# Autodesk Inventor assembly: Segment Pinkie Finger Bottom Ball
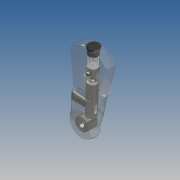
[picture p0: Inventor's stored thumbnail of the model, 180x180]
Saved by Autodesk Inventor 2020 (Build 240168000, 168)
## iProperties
Created: 2019-10
Part Number: Segment Pinkie Finger Bottom Ball
Document SubType Name: Assembly
Designer: yello
Author: yello
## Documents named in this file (8)
- C:\Users\yello\Documents\Mechanical Hand\Prototype 2 (Realistic Hand)\Segment Pinkie Finger Bottom Ball.iam
- C:\Users\yello\Documents\Mechanical Hand\Prototype 2 (Realistic Hand)\Segment Pinkie Finger Bottom.ipt
- C:\Users\yello\Documents\Mechanical Hand\Prototype 2 (Realistic Hand)\Lock.ipt
- C:\Users\yello\Documents\Mechanical Hand\Prototype 2 (Realistic Hand)\Ball.ipt
- C:\Users\yello\Documents\Mechanical Hand\Prototype 2 (Realistic Hand)\Plug 3.ipt
- C:\Users\yello\Documents\Mechanical Hand\Prototype 2 (Realistic Hand)\Push Part.ipt
- C:\Users\yello\Documents\Mechanical Hand\Prototype 2 (Realistic Hand)\Spring.ipt
- C:\Users\yello\Documents\Mechanical Hand\Prototype 2 (Realistic Hand)\Bearings.iam
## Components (8 placed, 7 different names)
1. Segment Pinkie Finger Bottom:1 — Mate:5, Mate:6, Mate:9, Mate:10, Mate:11, Mate:12, Mate:13, Mate:14, Flush:1
2. Ball:1 — Mate:6
3. Ball:2 — Mate:5
4. Push Part:1 — Mate:7, Mate:8, Mate:9
5. Lock:1 — Mate:7, Mate:8, Mate:10
6. Spring:1 — Mate:11
7. Plug 3:1 — Mate:12, Mate:13
8. Bearings:1 [sub-assembly] — Mate:14, Flush:1
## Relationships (11: Mate 10, Flush 1)
- Mate:5: Segment Pinkie Finger Bottom:1 ↔ Ball:2
- Mate:6: Segment Pinkie Finger Bottom:1 ↔ Ball:1
- Mate:7: Push Part:1 ↔ Lock:1
- Mate:8: Push Part:1 ↔ Lock:1
- Mate:9: Segment Pinkie Finger Bottom:1 ↔ Push Part:1
- Mate:10: Segment Pinkie Finger Bottom:1 ↔ Lock:1
- Mate:11: Segment Pinkie Finger Bottom:1 ↔ Spring:1
- Mate:12: Segment Pinkie Finger Bottom:1 ↔ Plug 3:1
- Mate:13: Segment Pinkie Finger Bottom:1 ↔ Plug 3:1
- Mate:14: Segment Pinkie Finger Bottom:1 ↔ Bearings:1
- Flush:1: Segment Pinkie Finger Bottom:1 ↔ Bearings:1
